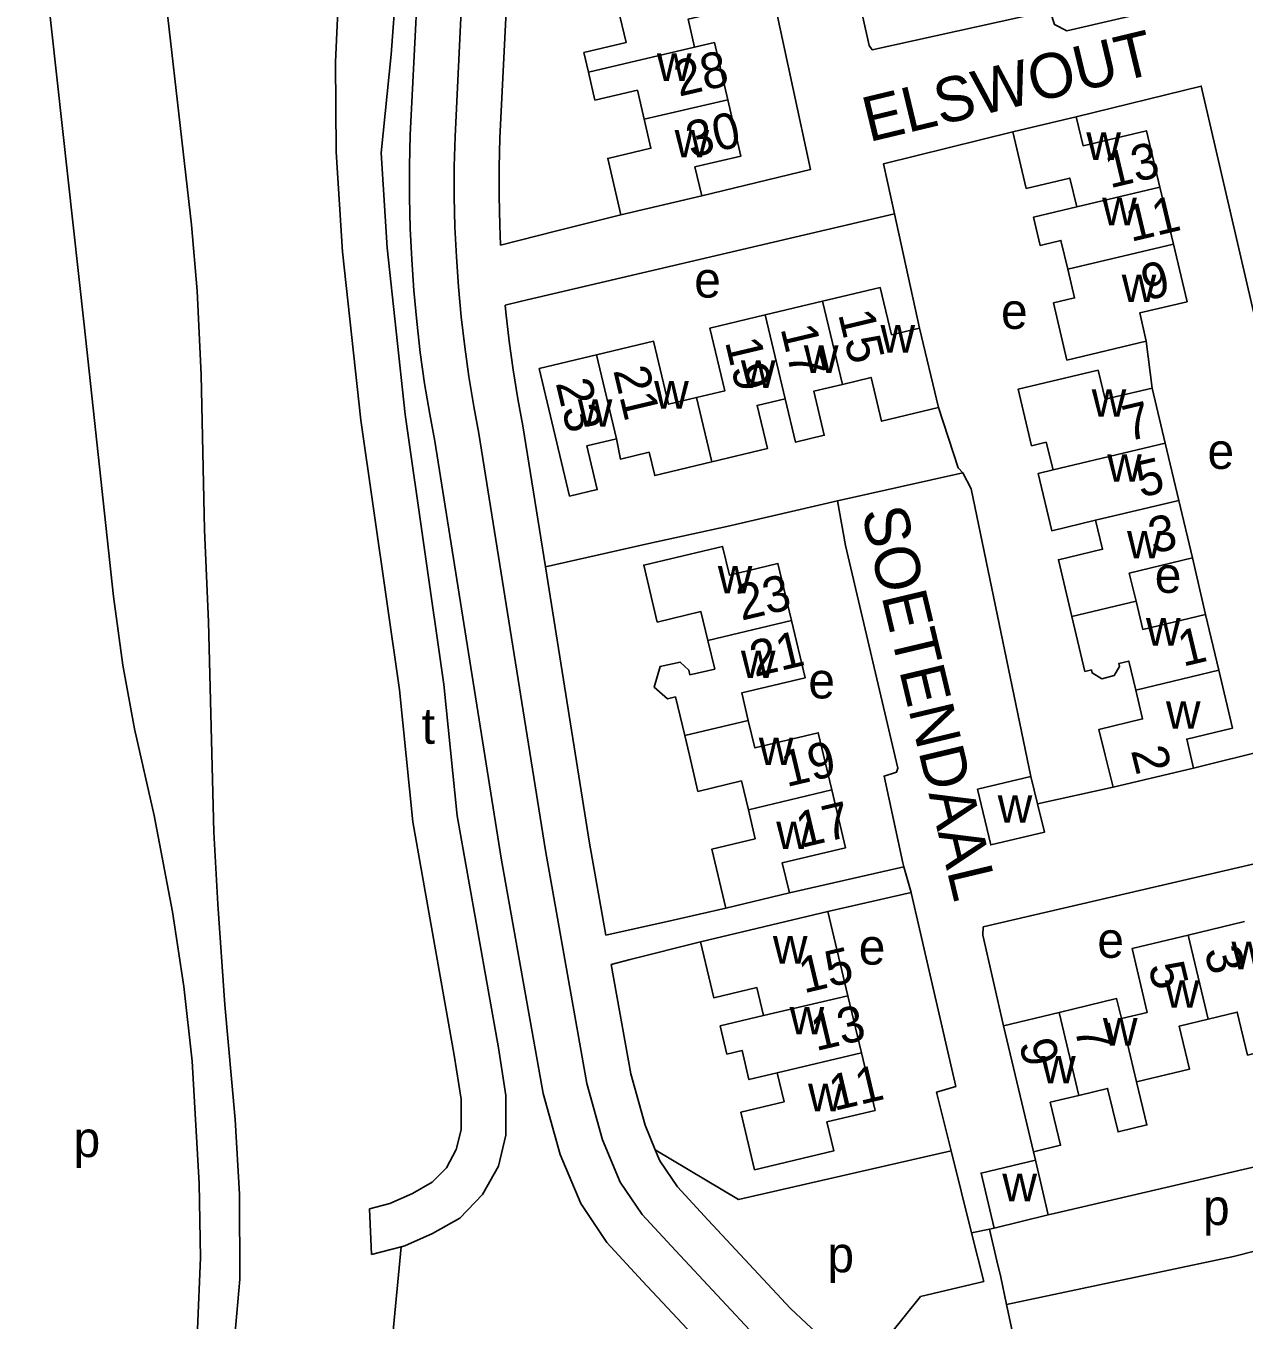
# Model space of a CAD drawing. Extents: x 157646 to 159241, y 379213 to 381217.
# Drawn here: x 158026.1 to 158162.1, y 380686.9 to 380831.4 of the extents above; entities that cross this region are included whole.
import ezdxf

# ---------------------------------------------------------------- set-up
doc = ezdxf.new("R2010")
doc.units = 0
for name, color, linetype in [('BLT_Basislijn', 7, 'Continuous'), ('BLT_Bebouwing', 7, 'Continuous'), ('BLT_Centroide', 7, 'Continuous'), ('BLT_Huisnummer', 7, 'Continuous'), ('BLT_Huisnummer_ tussenligend', 7, 'Continuous'), ('BLT_Onderverdeling_panden', 7, 'Continuous'), ('BLT_Straatnaam', 7, 'Continuous')]:
    doc.layers.add(name, color=color, linetype=linetype)

msp = doc.modelspace()

# ---------------------------------------------------------------- linework, layer by layer
at = {"layer": 'BLT_Basislijn'}
for p, q in [((158069.85, 380836.59), (158068.98, 380819.25)), ((158074.84, 380836.35), (158073.98, 380819.07)), ((158081.4, 380800.69), (158123.07, 380810.44)), ((158092.5, 380810.34), (158085.36, 380808.53)), ((158123.07, 380810.44), (158125.84, 380797.68)), ((158085.36, 380808.53), (158079.07, 380806.94)), ((158079.57, 380800.26), (158081.4, 380800.69)), ((158151.83, 380790.98), (158151.19, 380796.23)), ((158081.56, 380786.77), (158084.08, 380771.01)), ((158071.71, 380785.07), (158079.14, 380738.5)), ((158076.64, 380785.92), (158084.07, 380739.33)), ((158130.7, 380781.53), (158116.69, 380778.38)), ((158157.81, 380765.7), (158156.34, 380772.01)), ((158084.08, 380771.01), (158089, 380740.16)), ((158165, 380750.66), (158156.46, 380748.53)), ((158147.47, 380746.4), (158139.05, 380744.54)), ((158089, 380740.16), (158090.84, 380729.9)), ((158084.07, 380739.33), (158088.72, 380713.31)), ((158079.14, 380738.5), (158083.84, 380712.2)), ((158111.32, 380734.6), (158124.11, 380737.53)), ((158124.91, 380734.65), (158124.11, 380737.53)), ((158115.63, 380732.54), (158124.91, 380734.65)), ((158098.35, 380731.58), (158104.24, 380732.9)), ((158090.84, 380729.9), (158098.35, 380731.58)), ((158093.56, 380727.16), (158101.4, 380729.16)), ((158091.42, 380726.62), (158093.56, 380727.16)), ((158091.42, 380726.62), (158093.6, 380714.42)), ((158127.75, 380712.34), (158129.93, 380712.98)), ((158127.75, 380712.34), (158129.39, 380705.8)), ((158105.64, 380700.36), (158129.39, 380705.8)), ((158129.39, 380705.8), (158131.67, 380696.65)), ((158138.6, 380705.7), (158138.82, 380704.77)), ((158064.44, 380699.34), (158064.64, 380694.21)), ((158131.67, 380696.65), (158133.67, 380697.05)), ((158131.67, 380696.65), (158133.03, 380691.23)), ((158133.67, 380697.05), (158134.21, 380697.16)), ((158133.67, 380697.05), (158134.5, 380693.52)), ((158135.59, 380688.64), (158160.93, 380693.99)), ((158160.93, 380693.99), (158163.43, 380694.64)), ((158134.5, 380693.52), (158134.93, 380691.68)), ((158135.59, 380688.64), (158134.93, 380691.68)), ((158137.16, 380681.35), (158135.59, 380688.64))]:
    msp.add_line(p, q, dxfattribs=at)
for points in [[(158049.07, 380681.34), (158049.96, 380691.48), (158049.9, 380700.95), (158049.44, 380709.31), (158048.28, 380722.11), (158047.5, 380733.35), (158047.05, 380741.4), (158046.43, 380764.87), (158046, 380775.14), (158045.62, 380792.48), (158045.17, 380801.85), (158044.53, 380809.2), (158040.63, 380843.49), (158039.23, 380856.84), (158038.82, 380860.73), (158038.88, 380862.51)], [(158045.23, 380685.9), (158045.55, 380693.84), (158045.39, 380702.14), (158044.61, 380715.8), (158043.71, 380724.16), (158042.44, 380732.51), (158040.38, 380743.25), (158038.2, 380752.94), (158036.88, 380760.03), (158035.82, 380767.7), (158032.55, 380798.05), (158028.93, 380831.12), (158025.98, 380858.02), (158025.62, 380861.15)], [(158064.44, 380699.34), (158066.71, 380699.94), (158069.23, 380701.04), (158071.42, 380702.29), (158073.01, 380703.92), (158074.12, 380705.94), (158074.66, 380708.15), (158074.66, 380711.59), (158073.9, 380716.48), (158069.27, 380742.54), (158067.78, 380757.3), (158063.47, 380787.39), (158061.42, 380806.21), (158060.71, 380817.36), (158060.63, 380827.42), (158061.17, 380838.82), (158061.69, 380856.58)], [(158067.96, 380695.1), (158068.36, 380695.21), (158071.48, 380696.56), (158074.51, 380698.3), (158077.06, 380700.92), (158078.82, 380704.11), (158079.66, 380707.55), (158079.66, 380711.98), (158078.83, 380717.31), (158074.23, 380743.23), (158072.74, 380757.9), (158068.43, 380788.02), (158066.4, 380806.64), (158065.72, 380817.26), (158066.83, 380828.25), (158067.41, 380835.8), (158068.48, 380853.49)], [(158101.53, 380812.45), (158113.68, 380815.39), (158109.72, 380833.7), (158109.89, 380835.09), (158111.89, 380835.52), (158111.98, 380835.87), (158109.6, 380846.96)], [(158156.35, 380847.87), (158159.2, 380834.81), (158142.3, 380830.88), (158140.92, 380831.58), (158140.5, 380832.96), (158139.5, 380832.94), (158120.57, 380828.76), (158120.25, 380829.24), (158117.95, 380839.44), (158120.48, 380843.58)], [(158080.2, 380844.1), (158079.83, 380836.11), (158078.97, 380818.88)], [(158170.71, 380766.93), (158157.33, 380824.72), (158143.35, 380821.29)], [(158136.27, 380819.61), (158121.85, 380816.04), (158123.07, 380810.44)], [(158068.98, 380819.25), (158068.9, 380815.78), (158068.9, 380812.3), (158068.98, 380808.82), (158069.14, 380805.35), (158069.38, 380801.87), (158069.7, 380798.41), (158070.1, 380794.95), (158070.58, 380791.5), (158071.15, 380788.07), (158071.71, 380785.07)], [(158073.98, 380819.07), (158073.9, 380815.72), (158073.9, 380812.36), (158073.97, 380808.99), (158074.13, 380805.63), (158074.36, 380802.28), (158074.67, 380798.93), (158075.06, 380795.59), (158075.53, 380792.26), (158076.07, 380788.93), (158076.64, 380785.92)], [(158078.97, 380818.88), (158078.9, 380815.66), (158078.9, 380812.41), (158078.97, 380809.17), (158079.07, 380806.94)], [(158079.57, 380800.26), (158079.65, 380799.45), (158080.02, 380796.22), (158080.47, 380793.01), (158081, 380789.8), (158081.56, 380786.77)], [(158130.7, 380781.53), (158130.17, 380782.09), (158127.96, 380788.8)], [(158130.7, 380781.53), (158131.64, 380779.74), (158138.29, 380747.6)], [(158084.08, 380771.01), (158095.64, 380773.61), (158104.33, 380775.51), (158116.69, 380778.38)], [(158116.69, 380778.38), (158117.6, 380773.42), (158123.43, 380748.55), (158123.27, 380748.08), (158121.9, 380747.66), (158123.99, 380737.96), (158124.11, 380737.53)], [(158172.05, 380739.92), (158132.97, 380730.81), (158132.92, 380729.89), (158135.23, 380719.77)], [(158129.93, 380712.98), (158124.96, 380734.45), (158124.91, 380734.65)], [(158096.35, 380705.91), (158095.2, 380708.67), (158093.6, 380714.42)], [(158098.59, 380694.66), (158094.89, 380698.68), (158092.44, 380702.31), (158090.46, 380707.03), (158088.72, 380713.31)], [(158094.92, 380691.26), (158090.95, 380695.58), (158088.02, 380699.92), (158085.73, 380705.38), (158083.84, 380712.2)], [(158140.24, 380698.65), (158140.88, 380698.8), (158179.27, 380707.73)], [(158096.35, 380705.91), (158105.64, 380700.36)], [(158102.25, 380698.06), (158098.82, 380701.79), (158096.86, 380704.69), (158096.35, 380705.91)], [(158102.25, 380698.06), (158111.45, 380688.21), (158119.11, 380681.02)], [(158017.27, 380464.28), (158014.9, 380490.94), (158012.62, 380512.45), (158012.29, 380527.44), (158014.09, 380548.63), (158015.51, 380558.14), (158018.58, 380571.64), (158021.46, 380580.95), (158026.03, 380590.36), (158038.37, 380609.77), (158046.68, 380624.76), (158055.48, 380641.87), (158063.63, 380662.24), (158066.96, 380684.53), (158067.96, 380695.1)], [(158064.64, 380694.21), (158067.96, 380695.1)], [(158098.59, 380694.66), (158107.9, 380684.68), (158120.76, 380672.61), (158122.64, 380670.93)], [(158094.92, 380691.26), (158104.36, 380681.15), (158117.38, 380668.92), (158119.31, 380667.2)], [(158119.11, 380681.02), (158125.98, 380689.55), (158133.03, 380691.23)]]:
    msp.add_lwpolyline(points, dxfattribs=at)
at = {"layer": 'BLT_Bebouwing'}
for p, q in [((158136.27, 380819.61), (158143.35, 380821.29)), ((158101.53, 380812.45), (158092.5, 380810.34)), ((158152.7, 380813.43), (158154.21, 380807.07)), ((158115.04, 380800.68), (158108.63, 380799.15)), ((158127.96, 380788.8), (158125.84, 380797.68)), ((158089.77, 380794.69), (158083.38, 380793.17)), ((158083.38, 380793.17), (158086.78, 380778.92)), ((158153.29, 380784.82), (158151.83, 380790.98)), ((158140.02, 380784.95), (158140.79, 380781.85)), ((158154.81, 380778.43), (158153.29, 380784.82)), ((158156.34, 380772.01), (158154.81, 380778.43)), ((158159.29, 380759.48), (158157.81, 380765.7)), ((158132.34, 380746.19), (158138.29, 380747.6)), ((158138.29, 380747.6), (158139.05, 380744.54)), ((158156.46, 380748.53), (158147.47, 380746.4)), ((158111.32, 380734.6), (158104.24, 380732.9)), ((158115.63, 380732.54), (158101.4, 380729.16)), ((158162.14, 380731.41), (158155.86, 380729.9)), ((158119.37, 380716.75), (158117.86, 380723.13)), ((158141.44, 380721.26), (158135.23, 380719.77)), ((158135.23, 380719.77), (158138.6, 380705.7))]:
    msp.add_line(p, q, dxfattribs=at)
for points in [[(158105.61, 380840.03), (158107.06, 380833.82), (158100.01, 380832.17), (158100.74, 380829.04)], [(158088.88, 380826.27), (158088.37, 380828.46), (158093.08, 380829.56), (158092.17, 380833.45), (158092.79, 380833.59), (158092.02, 380836.9), (158096.22, 380837.84)], [(158100.74, 380829.04), (158102.96, 380829.56), (158104.45, 380823.19)], [(158095.11, 380821.01), (158094.35, 380824.25), (158089.61, 380823.14), (158088.88, 380826.27)], [(158104.45, 380823.19), (158105.92, 380816.89), (158100.77, 380815.68), (158101.53, 380812.45)], [(158092.5, 380810.34), (158091.03, 380816.63), (158095.86, 380817.76), (158095.11, 380821.01)], [(158143.35, 380821.29), (158144.12, 380818.05), (158151.2, 380819.73), (158152.7, 380813.43)], [(158143.41, 380811.22), (158142.64, 380814.44), (158137.77, 380813.29), (158136.27, 380819.61)], [(158142.41, 380804.26), (158141.65, 380807.47), (158139.64, 380807), (158139.33, 380806.92), (158138.58, 380810.07), (158143.41, 380811.22)], [(158154.21, 380807.07), (158155.74, 380800.63), (158150.45, 380799.37), (158151.19, 380796.23)], [(158151.19, 380796.23), (158142.33, 380794.12), (158140.82, 380800.49), (158143.18, 380801.05), (158142.41, 380804.26)], [(158125.84, 380797.68), (158122.74, 380796.94), (158121.48, 380802.21), (158115.04, 380800.68)], [(158108.63, 380799.15), (158102.43, 380797.67), (158104.1, 380790.67), (158100.96, 380789.92)], [(158100.96, 380789.92), (158097.83, 380789.18), (158096.15, 380796.22), (158089.77, 380794.69)], [(158117.25, 380791.4), (158120.45, 380792.17), (158121.62, 380787.28), (158127.96, 380788.8)], [(158151.83, 380790.98), (158146.59, 380789.73), (158145.81, 380792.98), (158136.87, 380790.85), (158138.37, 380784.55), (158140.02, 380784.95)], [(158110.86, 380789.8), (158112.02, 380784.94), (158115.22, 380785.71), (158114.04, 380790.64), (158117.25, 380791.4)], [(158102.68, 380782.74), (158108.87, 380784.22), (158107.72, 380789.05), (158110.86, 380789.8)], [(158086.78, 380778.92), (158089.87, 380779.65), (158088.7, 380784.53), (158092, 380785.31)], [(158092, 380785.31), (158092.45, 380783.05), (158095.66, 380783.82), (158096.28, 380781.22), (158102.68, 380782.74)], [(158140.79, 380781.85), (158139.11, 380781.45), (158140.63, 380775.06), (158145.52, 380776.22)], [(158145.52, 380776.22), (158146.3, 380772.99), (158141.37, 380771.81), (158142.88, 380765.48)], [(158111.56, 380765.04), (158110.05, 380771.4), (158104.62, 380770.11), (158103.86, 380773.31), (158095.06, 380771.22), (158096.57, 380764.86), (158101.45, 380766.02), (158102.21, 380762.81)], [(158150.04, 380767.18), (158149.29, 380770.33), (158156.34, 380772.01)], [(158157.81, 380765.7), (158150.79, 380764.03), (158150.04, 380767.18)], [(158106.73, 380753.87), (158106, 380756.94), (158113.09, 380758.63), (158111.56, 380765.04)], [(158142.88, 380765.48), (158144.34, 380759.34), (158145.05, 380759.51), (158145.13, 380759.18), (158146.22, 380758.51), (158147.61, 380758.87), (158148.21, 380759.9), (158148.13, 380760.24), (158149.23, 380760.5), (158150.01, 380757.26)], [(158102.21, 380762.81), (158102.98, 380759.61), (158100.21, 380758.95)], [(158100.21, 380758.95), (158100.08, 380759.48), (158099.13, 380760.38), (158096.88, 380759.9), (158096.22, 380757.58), (158097.71, 380756.28), (158098.6, 380756.49), (158099.63, 380752.18)], [(158159.29, 380759.48), (158160.83, 380753.01), (158155.71, 380751.79), (158156.13, 380750), (158156.46, 380748.53)], [(158147.47, 380746.4), (158146.58, 380750), (158145.9, 380752.86), (158150.78, 380754.03), (158150.01, 380757.26)], [(158116.07, 380746.11), (158115.14, 380750), (158114.54, 380752.49), (158107.47, 380750.8), (158106.73, 380753.87)], [(158099.63, 380752.18), (158100.15, 380750), (158101.11, 380745.95), (158105.97, 380747.11), (158106.74, 380743.88)], [(158116.07, 380746.11), (158117.61, 380739.66), (158110.52, 380737.97), (158111.32, 380734.6)], [(158139.05, 380744.54), (158139.81, 380741.39), (158133.81, 380739.97), (158132.34, 380746.19)], [(158104.24, 380732.9), (158102.66, 380739.49), (158107.51, 380740.65), (158106.74, 380743.88)], [(158117.86, 380723.13), (158115.63, 380732.54)], [(158155.86, 380729.9), (158149.59, 380728.39), (158151.3, 380721.27), (158148.4, 380720.57)], [(158101.4, 380729.16), (158102.88, 380722.9), (158107.68, 380724.03), (158108.42, 380720.9)], [(158148.4, 380720.57), (158147.86, 380722.8), (158141.44, 380721.26)], [(158158.11, 380720.52), (158161.34, 380721.29), (158162.5, 380716.49), (158165.54, 380717.22)], [(158108.42, 380720.9), (158103.6, 380719.75), (158104.35, 380716.61), (158106.04, 380717.01), (158106.8, 380713.77), (158109.97, 380714.52)], [(158150.09, 380713.52), (158156.03, 380714.94), (158154.87, 380719.74), (158158.11, 380720.52)], [(158109.97, 380714.52), (158110.73, 380711.29), (158105.92, 380710.14), (158107.44, 380703.7), (158116.27, 380705.8), (158115.51, 380709.03), (158120.9, 380710.31), (158119.37, 380716.75)], [(158143.66, 380712), (158146.86, 380712.77), (158148.03, 380707.92), (158151.26, 380708.69), (158150.09, 380713.52)], [(158138.6, 380705.7), (158141.62, 380706.42), (158140.46, 380711.23), (158143.66, 380712)], [(158134.21, 380697.16), (158132.74, 380703.32), (158138.82, 380704.77)], [(158138.82, 380704.77), (158140.24, 380698.65)], [(158140.24, 380698.65), (158134.21, 380697.16)]]:
    msp.add_lwpolyline(points, dxfattribs=at)
at = {"layer": 'BLT_Onderverdeling_panden'}
for p, q in [((158088.88, 380826.27), (158100.74, 380829.04)), ((158095.11, 380821.01), (158104.45, 380823.19)), ((158143.41, 380811.22), (158152.7, 380813.43)), ((158142.41, 380804.26), (158154.21, 380807.07)), ((158117.25, 380791.4), (158115.04, 380800.68)), ((158110.86, 380789.8), (158108.63, 380799.15)), ((158089.77, 380794.69), (158092, 380785.31)), ((158100.96, 380789.92), (158102.68, 380782.74)), ((158140.79, 380781.85), (158153.29, 380784.82)), ((158145.52, 380776.22), (158154.81, 380778.43)), ((158150.04, 380767.18), (158142.88, 380765.48)), ((158102.21, 380762.81), (158111.56, 380765.04)), ((158150.01, 380757.26), (158159.29, 380759.48)), ((158106.73, 380753.87), (158099.63, 380752.18)), ((158106.74, 380743.88), (158116.07, 380746.11)), ((158158.11, 380720.52), (158155.86, 380729.9)), ((158108.42, 380720.9), (158117.86, 380723.13)), ((158143.66, 380712), (158141.44, 380721.26)), ((158150.09, 380713.52), (158148.4, 380720.57)), ((158109.97, 380714.52), (158119.37, 380716.75))]:
    msp.add_line(p, q, dxfattribs=at)

# ---------------------------------------------------------------- texts
at = {"layer": 'BLT_Centroide'}
for s, p in [('w', (158096.53, 380825.28)), ('w', (158098.5, 380816.75)), ('w', (158144.49, 380816.47)), ('w', (158146.26, 380809.16)), ('e', (158100.7, 380801.09)), ('w', (158148.44, 380800.59)), ('e', (158134.96, 380797.6)), ('w', (158121.5, 380794.95)), ('w', (158112.94, 380792.67)), ('w', (158105.91, 380791)), ('w', (158096.22, 380788.69)), ('w', (158145.09, 380787.78)), ('w', (158087.69, 380786.66)), ('e', (158158.02, 380781.96)), ('w', (158146.82, 380780.53)), ('w', (158149.03, 380771.97)), ('w', (158103.33, 380768.06)), ('e', (158152.13, 380768.12)), ('w', (158151.15, 380762.22)), ('w', (158105.91, 380758.59)), ('e', (158113.44, 380756.33)), ('w', (158153.38, 380752.94)), ('t', (158070.26, 380751.26)), ('w', (158107.91, 380748.88)), ('w', (158134.59, 380742.45)), ('w', (158109.85, 380739.5)), ('e', (158145.72, 380727.36)), ('w', (158109.48, 380726.72)), ('e', (158119.07, 380726.6)), ('w', (158160.7, 380726.09)), ('w', (158153.25, 380721.78)), ('w', (158111.35, 380718.81)), ('w', (158146.34, 380717.55)), ('w', (158139.44, 380713.34)), ('w', (158113.41, 380710.22)), ('p', (158031.38, 380705.11)), ('w', (158135.11, 380700.17)), ('p', (158157.52, 380697.52)), ('p', (158115.57, 380692.24))]:
    msp.add_text(s, height=4, dxfattribs=at).set_placement(p)
at = {"layer": 'BLT_Huisnummer'}
for s, rotation, p in [('28', 13.1553, (158098.99, 380823.52)), ('30', 13.1553, (158100.33, 380816.7)), ('13', 13.3951, (158147.12, 380813.28)), ('9', 13.3951, (158151.18, 380800.74)), ('15', 283.4155, (158116.76, 380799.25)), ('19', 283.4106, (158104.12, 380796.16)), ('23', 283.4131, (158085.21, 380791.56)), ('21', 283.4106, (158091.64, 380792.96)), ('7', 13.3951, (158149.11, 380785.01)), ('3', 13.3951, (158151.98, 380772.47)), ('23', 13.4107, (158105.97, 380765)), ('21', 13.4478, (158107.45, 380758.71)), ('1', 13.3951, (158155.28, 380759.86)), ('19', 13.4478, (158111, 380746.41)), ('2', 283.8973, (158149.46, 380750.51)), ('17', 13.4478, (158112.65, 380739.62)), ('15', 13.3336, (158112.94, 380723.38)), ('5', 283.4984, (158151.39, 380726.44)), ('7', 283.4984, (158143.15, 380719.47)), ('9', 283.4956, (158136.95, 380717.85)), ('11', 13.3381, (158116.32, 380710.25))]:
    msp.add_text(s, height=4, rotation=rotation, dxfattribs=at).set_placement(p)
at = {"layer": 'BLT_Huisnummer_ tussenligend'}
for s, rotation, p in [('11', 13.3951, (158149.46, 380807.3)), ('17', 283.4155, (158110.32, 380797.65)), ('5', 13.3951, (158150.56, 380778.74)), ('3', 283.4984, (158157.66, 380728.18)), ('13', 13.3381, (158114.29, 380716.93))]:
    msp.add_text(s, height=4, rotation=rotation, dxfattribs=at).set_placement(p)
at = {"layer": 'BLT_Straatnaam'}
for s, rotation, p in [('ELSWOUT', 13.5158, (158120.21, 380818.44)), ('SOETENDAAL', 283.4111, (158119.35, 380777.17))]:
    msp.add_text(s, height=5, rotation=rotation, dxfattribs=at).set_placement(p)

doc.saveas('drawing.dxf')
